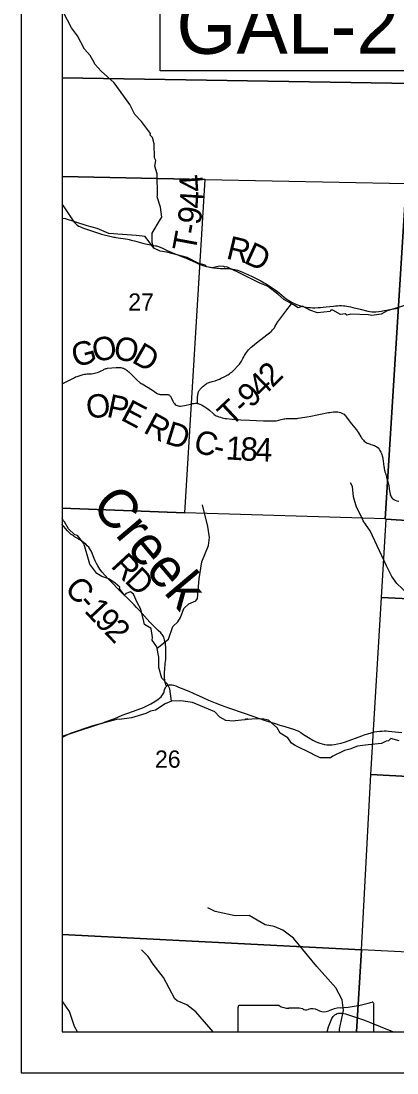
# Model space of a CAD drawing. Extents: x 0 to 34, y 0 to 22.
# Drawn here: x 2 to 2.913, y 14 to 16.555 of the extents above; entities that cross this region are included whole.
import ezdxf

# ---------------------------------------------------------------- set-up
doc = ezdxf.new("R2010")
doc.units = 0
for name, color, linetype in [('Default', 7, 'Continuous'), ('GM_X_County_Road', 7, 'Continuous'), ('GM_X_County_Road_Text', 7, 'Continuous'), ('GM_X_Minor_River', 7, 'Continuous'), ('GM_X_Minor_River_Text', 7, 'Continuous'), ('GM_X_Section', 7, 'Continuous'), ('GM_X_Section_Text', 7, 'Continuous'), ('GM_X_State_Route', 7, 'Continuous'), ('GM_X_State_Shield', 7, 'Continuous'), ('GM_X_Township_Road', 7, 'Continuous'), ('GM_X_Township_Road_Text', 7, 'Continuous'), ('SH_Cut_Line', 7, 'Continuous'), ('SH_Data', 7, 'Continuous'), ('TX_P_1', 7, 'Continuous')]:
    doc.layers.add(name, color=color, linetype=linetype)

msp = doc.modelspace()

# ---------------------------------------------------------------- linework, layer by layer
at = {"layer": 'Default'}
for points in [[(2.1, 19.5179), (2.1, 14.1), (5.687, 14.1), (5.785, 14.1504), (5.9145, 14.1963), (5.9273, 14.1959), (5.9341, 14.3014), (6.0001, 15.328), (6.0418, 15.9539), (6.0633, 16.2368), (6.0901, 16.6706), (6.1151, 17.0743), (6.1723, 18.0255), (6.1917, 18.3385), (6.2282, 18.9116), (6.2536, 19.3066), (5.4875, 19.3459), (4.7013, 19.3856), (4.4284, 19.3984), (3.7007, 19.4348)], [(2.1, 16.6219), (2.1, 16.4177), (2.9504, 16.4035), (2.9626, 16.5982)], [(2.1, 16.4177), (2.1, 16.178), (2.4468, 16.1708), (2.9352, 16.1608), (2.9504, 16.4035)], [(2.1, 16.178), (2.1, 15.3718), (2.3978, 15.3611), (2.4468, 16.1708)], [(2.1, 15.3718), (2.1, 14.3367), (2.8265, 14.2988), (2.8494, 14.7254), (2.8751, 15.155), (2.8868, 15.3457), (2.8841, 15.3459), (2.3978, 15.3611)], [(2.1, 14.3367), (2.1, 14.1), (2.815, 14.1), (2.8265, 14.2988)], [(2.815, 14.1), (3.8426, 14.1), (3.8519, 14.2476), (2.8265, 14.2988)]]:
    msp.add_lwpolyline(points, close=True, dxfattribs=at)
at = {"layer": 'GM_X_County_Road'}
for points in [[(2.1, 16.1097), (2.1071, 16.0992), (2.1231, 16.0749), (2.125, 16.0722), (2.1271, 16.0696), (2.129, 16.0672), (2.1314, 16.0643), (2.1339, 16.0619), (2.1367, 16.0596), (2.1402, 16.0573), (2.1442, 16.0552), (2.1477, 16.0536), (2.1519, 16.052), (2.1854, 16.041), (2.1903, 16.0395), (2.1954, 16.0381), (2.2187, 16.032), (2.222, 16.0313), (2.2252, 16.0307), (2.2279, 16.0301), (2.2306, 16.0297), (2.2594, 16.0253), (2.2624, 16.0247), (2.2652, 16.0241), (2.2676, 16.0235), (2.2705, 16.0227), (2.2752, 16.0214)], [(2.2752, 16.0214), (2.2923, 16.0165), (2.2955, 16.0157), (2.2982, 16.0151), (2.3263, 16.0097), (2.3288, 16.0091), (2.3312, 16.0084), (2.3336, 16.0076), (2.3357, 16.0069), (2.3379, 16.0061), (2.3399, 16.0053), (2.3423, 16.0043), (2.3548, 15.9983), (2.3666, 15.9928), (2.3964, 15.9813), (2.3993, 15.9801), (2.4027, 15.9787), (2.4061, 15.9773), (2.4098, 15.9757), (2.4247, 15.9688), (2.4312, 15.9659), (2.4371, 15.9636), (2.4418, 15.9618), (2.4468, 15.9602), (2.4509, 15.9591), (2.455, 15.9581), (2.4589, 15.9574), (2.4629, 15.9567), (2.4672, 15.9561), (2.4712, 15.9556), (2.4753, 15.9551), (2.4793, 15.9548), (2.4842, 15.9545), (2.5062, 15.9539), (2.509, 15.9537), (2.5114, 15.9534), (2.5138, 15.953), (2.5192, 15.9519), (2.5254, 15.9502), (2.5319, 15.948), (2.5381, 15.9455), (2.5452, 15.9424), (2.5521, 15.9392), (2.5594, 15.9356), (2.5822, 15.9243), (2.5866, 15.922), (2.5907, 15.9198), (2.5951, 15.9173), (2.5989, 15.915), (2.6029, 15.9123), (2.6078, 15.9091), (2.6147, 15.9044), (2.6225, 15.8985), (2.6276, 15.8942), (2.6332, 15.8896), (2.6393, 15.8844), (2.6402, 15.8837)], [(2.6402, 15.8837), (2.6429, 15.8817), (2.6458, 15.8796), (2.6483, 15.8779), (2.6502, 15.8767), (2.6588, 15.8719), (2.6693, 15.8669), (2.6741, 15.8649), (2.6785, 15.8633), (2.6835, 15.8619), (2.688, 15.8608), (2.6926, 15.86), (2.6975, 15.8595), (2.7033, 15.8593), (2.7082, 15.8591), (2.7133, 15.8591), (2.7219, 15.8594), (2.7272, 15.8597), (2.7336, 15.8602), (2.7409, 15.8609), (2.759, 15.8631), (2.764, 15.8636), (2.7689, 15.864), (2.7736, 15.8641), (2.7779, 15.8641), (2.783, 15.8638), (2.7872, 15.8634), (2.7913, 15.8628), (2.7955, 15.862), (2.8005, 15.8609), (2.8061, 15.8596), (2.824, 15.8551), (2.842, 15.8507), (2.8472, 15.8497), (2.8519, 15.8491), (2.8568, 15.8488), (2.8614, 15.8489), (2.8688, 15.8496), (2.8746, 15.8505), (2.896, 15.8544), (2.9157, 15.8581)], [(2.1, 15.6739), (2.1164, 15.6821), (2.1275, 15.6882), (2.1299, 15.6895), (2.1325, 15.6908), (2.1361, 15.6923), (2.1412, 15.6939), (2.1507, 15.6967), (2.154, 15.6974), (2.1574, 15.6979), (2.1609, 15.6981), (2.1641, 15.6983), (2.1676, 15.6984), (2.1715, 15.6987), (2.1751, 15.6991), (2.1786, 15.6997), (2.182, 15.7006), (2.186, 15.7017), (2.1894, 15.703), (2.1931, 15.7047), (2.2, 15.7084), (2.202, 15.7094), (2.204, 15.7102), (2.2061, 15.711), (2.208, 15.7115), (2.21, 15.7118), (2.231, 15.7137), (2.2335, 15.7139), (2.2358, 15.714), (2.2382, 15.714), (2.2405, 15.7138), (2.2427, 15.7136), (2.245, 15.7131), (2.2471, 15.7125), (2.2489, 15.7118), (2.2511, 15.7107), (2.2533, 15.7094), (2.2554, 15.7081), (2.2576, 15.7064), (2.2597, 15.7048), (2.262, 15.7029), (2.2644, 15.7007), (2.2669, 15.6982), (2.2821, 15.6828), (2.2895, 15.6767), (2.2914, 15.6753), (2.2939, 15.6738), (2.319, 15.6584), (2.3284, 15.6522), (2.3305, 15.651), (2.3325, 15.6501), (2.3344, 15.6494), (2.336, 15.6489), (2.3376, 15.6486), (2.3386, 15.6484), (2.3395, 15.6484), (2.3455, 15.6484), (2.3515, 15.6485), (2.3535, 15.6485), (2.3552, 15.6484), (2.3568, 15.6482), (2.3584, 15.6477), (2.3596, 15.647), (2.3607, 15.6462), (2.3617, 15.6453), (2.3627, 15.644), (2.3636, 15.6425), (2.3646, 15.6406), (2.3689, 15.6316), (2.3706, 15.6288), (2.3723, 15.6264), (2.3744, 15.6242), (2.3769, 15.6224), (2.3791, 15.6213), (2.3814, 15.6206), (2.3845, 15.6201), (2.3876, 15.62), (2.3919, 15.6203), (2.3967, 15.6211), (2.4123, 15.6249), (2.4167, 15.626), (2.4208, 15.6267), (2.4236, 15.6269), (2.4259, 15.627), (2.4283, 15.6267), (2.43, 15.6263), (2.4316, 15.6258), (2.4343, 15.6247), (2.4381, 15.6229), (2.4421, 15.6208), (2.4466, 15.6181), (2.451, 15.6151), (2.4541, 15.6126), (2.4575, 15.6098), (2.4669, 15.6017), (2.4688, 15.6), (2.4712, 15.5983), (2.4742, 15.5966), (2.4773, 15.5953), (2.4807, 15.5941), (2.4844, 15.5929), (2.4886, 15.5917), (2.492, 15.5909), (2.4956, 15.5903), (2.4992, 15.5898), (2.5129, 15.5883), (2.5229, 15.5874), (2.5276, 15.5871), (2.5335, 15.5868), (2.5547, 15.5862), (2.589, 15.5841), (2.6018, 15.5839), (2.6138, 15.5841), (2.6169, 15.5842), (2.6196, 15.5844), (2.6226, 15.5848), (2.6257, 15.5855), (2.6318, 15.5873), (2.6351, 15.5883), (2.6379, 15.589), (2.6406, 15.5894), (2.644, 15.5897), (2.668, 15.5899), (2.6704, 15.5901), (2.6728, 15.5904), (2.6998, 15.5947), (2.7468, 15.6041), (2.7503, 15.6047), (2.7543, 15.6053), (2.7586, 15.6058), (2.7622, 15.606), (2.7657, 15.6061), (2.7691, 15.6059), (2.7725, 15.6053), (2.776, 15.6042), (2.7795, 15.6029), (2.7823, 15.6015), (2.7845, 15.6002), (2.7867, 15.5983), (2.7883, 15.5965), (2.79, 15.5943), (2.8029, 15.5773), (2.8144, 15.5623), (2.8161, 15.5602), (2.8175, 15.5583), (2.8194, 15.5554), (2.8251, 15.5456), (2.8266, 15.5435), (2.828, 15.5415), (2.8314, 15.5374), (2.8336, 15.5352), (2.836, 15.5332), (2.8381, 15.5317), (2.8408, 15.5302), (2.8435, 15.5291), (2.8463, 15.5281), (2.8498, 15.5271), (2.8526, 15.5263), (2.8555, 15.5253), (2.8584, 15.5243), (2.8612, 15.5229), (2.8643, 15.5209), (2.867, 15.5185), (2.8697, 15.5152), (2.8717, 15.5121), (2.874, 15.5078), (2.8752, 15.505), (2.8763, 15.5024), (2.8773, 15.4993), (2.8779, 15.4965), (2.8784, 15.4931), (2.8813, 15.4734), (2.8817, 15.4708), (2.8821, 15.4682), (2.8839, 15.4606), (2.8848, 15.4571), (2.8876, 15.4471), (2.8902, 15.4387), (2.8909, 15.4363), (2.8917, 15.4333), (2.8924, 15.43), (2.8929, 15.4265), (2.8947, 15.4137), (2.8953, 15.4098), (2.8961, 15.4068), (2.8968, 15.4043), (2.8978, 15.4018), (2.899, 15.3996), (2.9006, 15.3972), (2.9028, 15.395), (2.9054, 15.3931), (2.9089, 15.3916), (2.9127, 15.3902), (2.9172, 15.3888)], [(2.3531, 14.9394), (2.3517, 14.9441), (2.3503, 14.9487), (2.3496, 14.9516), (2.3491, 14.9547), (2.3486, 14.959), (2.3485, 14.9629), (2.3485, 14.9673), (2.3486, 14.9709), (2.3488, 14.9746), (2.3493, 14.9802), (2.3504, 14.9948), (2.3513, 15.0048), (2.3515, 15.0106), (2.3516, 15.0181), (2.3517, 15.0257), (2.3516, 15.0307), (2.3513, 15.0351), (2.351, 15.0395), (2.3505, 15.0439), (2.3496, 15.0481), (2.3485, 15.0522), (2.3475, 15.0556), (2.3466, 15.0583), (2.3457, 15.0606), (2.3444, 15.0629), (2.3429, 15.0651), (2.3414, 15.0671), (2.3395, 15.069), (2.3331, 15.0752), (2.3131, 15.0952), (2.2876, 15.1233), (2.2806, 15.1308), (2.2744, 15.1372), (2.2675, 15.1442), (2.2599, 15.1517), (2.2453, 15.1652), (2.2116, 15.2005), (2.2033, 15.2096), (2.1971, 15.2169), (2.1916, 15.2241), (2.1867, 15.2317), (2.1832, 15.2377), (2.18, 15.244), (2.1777, 15.2496), (2.1735, 15.2606), (2.1716, 15.2652), (2.1696, 15.2695), (2.1673, 15.2734), (2.1644, 15.2771), (2.1609, 15.2807), (2.157, 15.2845), (2.1541, 15.287), (2.1515, 15.289), (2.148, 15.2916), (2.144, 15.2941), (2.1407, 15.2962), (2.1377, 15.298), (2.1302, 15.3025), (2.1271, 15.3045), (2.1246, 15.3062), (2.1218, 15.3084), (2.118, 15.3119), (2.113, 15.3169), (2.1081, 15.3224), (2.1041, 15.3272), (2.1002, 15.3319), (2.1, 15.3322)], [(2.1, 14.818), (2.1248, 14.8265), (2.1914, 14.8479), (2.1977, 14.85), (2.2045, 14.8526), (2.2277, 14.8615), (2.2458, 14.8689), (2.271, 14.8779), (2.2909, 14.8852), (2.2977, 14.8882), (2.3056, 14.892), (2.3149, 14.8967), (2.325, 14.9024), (2.3284, 14.9045), (2.3319, 14.9069), (2.3362, 14.9103), (2.3401, 14.9141), (2.3437, 14.9185), (2.3455, 14.9214), (2.3466, 14.9235), (2.3472, 14.9255), (2.348, 14.928), (2.3488, 14.9306), (2.3496, 14.9331), (2.3505, 14.9353), (2.3517, 14.9375), (2.3523, 14.9385), (2.3531, 14.9394), (2.354, 14.94), (2.355, 14.9409), (2.3573, 14.9421), (2.36, 14.9428), (2.3623, 14.9432), (2.3646, 14.9432), (2.3671, 14.9428), (2.3704, 14.9421), (2.3757, 14.9403), (2.3826, 14.9376), (2.3889, 14.935), (2.4073, 14.9275), (2.4181, 14.9229), (2.4416, 14.912), (2.4553, 14.9057), (2.4717, 14.8988), (2.4862, 14.8932), (2.5037, 14.8867), (2.5419, 14.8737), (2.5926, 14.8566), (2.6168, 14.8487), (2.6286, 14.8449), (2.6405, 14.8415), (2.654, 14.8376), (2.6616, 14.835), (2.6684, 14.8324), (2.674, 14.83), (2.6792, 14.8272), (2.6838, 14.8241), (2.6902, 14.8201), (2.698, 14.8151), (2.7087, 14.8084), (2.7153, 14.8049), (2.7205, 14.8026), (2.7259, 14.8008), (2.7313, 14.7993), (2.7367, 14.7981), (2.7426, 14.7973), (2.7485, 14.797), (2.7547, 14.7972), (2.7612, 14.7978), (2.7684, 14.7993), (2.7774, 14.8015), (2.7877, 14.8044), (2.8273, 14.8189), (2.8354, 14.8219), (2.8424, 14.8242), (2.8501, 14.8265), (2.8574, 14.8284), (2.8642, 14.8295), (2.8711, 14.8303), (2.8765, 14.8307), (2.8823, 14.8309), (2.8869, 14.8309), (2.8921, 14.8306), (2.9002, 14.8299), (2.925, 14.827)]]:
    msp.add_lwpolyline(points, dxfattribs=at)
at = {"layer": 'GM_X_Minor_River'}
for points in [[(2.3146, 16.2822), (2.2923, 16.3118), (2.2764, 16.3281), (2.2646, 16.3524), (2.2283, 16.4021), (2.2253, 16.4059), (2.1943, 16.4339), (2.1799, 16.4495), (2.1742, 16.4601), (2.1678, 16.4719), (2.1538, 16.4874), (2.1371, 16.5193), (2.1227, 16.5387), (2.1023, 16.5778), (2.1, 16.5796)], [(2.9346, 15.8653), (2.8896, 15.8511), (2.8745, 15.8435), (2.8518, 15.8404), (2.8435, 15.8419), (2.8011, 15.8433), (2.7913, 15.841), (2.7875, 15.844), (2.7758, 15.8428), (2.7569, 15.8534), (2.752, 15.8527), (2.7505, 15.85), (2.7202, 15.8465), (2.7013, 15.8533), (2.6832, 15.8624), (2.673, 15.8589), (2.662, 15.8657), (2.6382, 15.879), (2.6234, 15.8919), (2.5985, 15.9112), (2.5799, 15.9184), (2.541, 15.9377), (2.4998, 15.9581), (2.4948, 15.9577), (2.4922, 15.9592), (2.4816, 15.9603), (2.4638, 15.9557), (2.4514, 15.958), (2.4468, 15.9625), (2.4298, 15.967), (2.4033, 15.981), (2.3538, 15.9942), (2.3379, 15.9961), (2.3224, 16.0033), (2.3183, 16.0177), (2.3182, 16.0401), (2.339, 16.0744), (2.342, 16.0786), (2.3386, 16.1029), (2.3306, 16.1287), (2.3318, 16.1314), (2.331, 16.1842), (2.3253, 16.2032), (2.3271, 16.2169), (2.3245, 16.2229), (2.3233, 16.2568), (2.3195, 16.2723), (2.3135, 16.2784), (2.3146, 16.2822)], [(2.3224, 16.0033), (2.3016, 16.0321), (2.2793, 16.0347), (2.2131, 16.0395), (2.1852, 16.0512), (2.1602, 16.0576), (2.1058, 16.0754), (2.1, 16.0753)], [(3.1037, 14.8257), (3.0772, 14.885), (3.0702, 14.9175), (3.0642, 14.9431), (3.0482, 14.9873), (3.0249, 15.029), (2.9823, 15.0843), (2.9647, 15.113), (2.9527, 15.1422), (2.9405, 15.1631), (2.9129, 15.189), (2.9002, 15.2061), (2.8874, 15.2323), (2.848, 15.3171), (2.831, 15.3412), (2.8274, 15.3493), (2.815, 15.3744), (2.8078, 15.3997), (2.8048, 15.4248), (2.8005, 15.4333)], [(2.3308, 15.0319), (2.358, 15.0541), (2.3687, 15.0842), (2.3808, 15.0956), (2.3875, 15.1067), (2.395, 15.1285), (2.4074, 15.1399), (2.4247, 15.1473), (2.4282, 15.1529), (2.4327, 15.2006), (2.4389, 15.2414), (2.4552, 15.2811), (2.4577, 15.3008), (2.4536, 15.3275), (2.4408, 15.3803)], [(2.3654, 14.9035), (2.3612, 14.9328), (2.3559, 14.9442), (2.3423, 14.9594), (2.3343, 14.9848), (2.3347, 15.0103), (2.3297, 15.035), (2.3188, 15.0517), (2.3195, 15.0581), (2.3161, 15.0794), (2.2998, 15.0896), (2.2979, 15.0964), (2.2907, 15.1265), (2.2824, 15.1428), (2.2729, 15.1633), (2.2661, 15.169), (2.2548, 15.1644), (2.2533, 15.1625), (2.2514, 15.1606), (2.2389, 15.1773), (2.24, 15.1799), (2.2283, 15.1902), (2.2132, 15.2004), (2.1961, 15.2057), (2.1837, 15.2136), (2.167, 15.236), (2.1609, 15.2584), (2.1522, 15.2865), (2.1375, 15.3055), (2.131, 15.3074), (2.1155, 15.3218), (2.1053, 15.3392), (2.1034, 15.3415), (2.1, 15.3472)], [(2.4829, 14.8643), (2.4709, 14.8776), (2.4459, 14.8882), (2.4168, 14.8999), (2.3881, 14.9044), (2.3654, 14.9035), (2.3503, 14.8967), (2.3269, 14.8814), (2.3148, 14.8791), (2.3034, 14.873), (2.2679, 14.8627), (2.2388, 14.8584), (2.235, 14.8595), (2.1742, 14.8431), (2.1194, 14.8243), (2.1, 14.8153)], [(2.9185, 14.8072), (2.8981, 14.8129), (2.8928, 14.8072), (2.8868, 14.8064), (2.8751, 14.8006), (2.8429, 14.7975), (2.8168, 14.794), (2.7987, 14.7868), (2.7859, 14.7837), (2.7575, 14.7692), (2.7518, 14.7658), (2.7265, 14.7653), (2.708, 14.7748), (2.7053, 14.7763), (2.6656, 14.7959), (2.6566, 14.8013), (2.6479, 14.8138), (2.6297, 14.8251), (2.6221, 14.8388), (2.6013, 14.857), (2.5858, 14.8604), (2.5605, 14.8595), (2.5518, 14.8588), (2.5495, 14.861), (2.5473, 14.858), (2.545, 14.8603), (2.5439, 14.858), (2.52, 14.8556), (2.517, 14.8549), (2.4974, 14.8564), (2.4827, 14.8644)], [(2.7734, 14.1), (2.7736, 14.106), (2.7829, 14.1516), (2.7796, 14.1779), (2.7642, 14.2065), (2.7185, 14.2585), (2.662, 14.3271), (2.6361, 14.3469), (2.6149, 14.3556), (2.5931, 14.3601), (2.5541, 14.3822), (2.52, 14.3817), (2.4716, 14.392), (2.4533, 14.401)], [(2.4663, 14.1), (2.4244, 14.1481), (2.403, 14.1659), (2.3795, 14.175), (2.3736, 14.1797), (2.3461, 14.2319), (2.3206, 14.2642), (2.3087, 14.2832), (2.2925, 14.2992)], [(2.137, 14.1), (2.1301, 14.1126), (2.1173, 14.1494), (2.1, 14.1751)]]:
    msp.add_lwpolyline(points, dxfattribs=at)
at = {"layer": 'GM_X_Section'}
for points in [[(2.9352, 16.1608), (2.8841, 15.3459), (2.3978, 15.3611), (2.4468, 16.1708)], [(3.0046, 16.1593), (2.9664, 15.604), (2.9483, 15.3412), (2.8868, 15.3457), (2.8841, 15.3459), (2.9352, 16.1608)], [(2.9483, 15.3412), (3.9173, 15.2973), (3.9051, 15.1052), (2.8751, 15.155), (2.8868, 15.3457)], [(2.8751, 15.155), (3.9051, 15.1052), (3.8776, 14.6701), (2.8494, 14.7254)], [(3.8776, 14.6701), (3.8519, 14.2476), (2.8265, 14.2988), (2.8494, 14.7254)]]:
    msp.add_lwpolyline(points, close=True, dxfattribs=at)
at = {"layer": 'GM_X_State_Route'}
msp.add_lwpolyline([(2.7434, 14.1), (2.7469, 14.112), (2.7482, 14.1161), (2.7496, 14.1202), (2.7513, 14.1245), (2.753, 14.1283), (2.7549, 14.132), (2.7568, 14.135), (2.7583, 14.1372), (2.7603, 14.1393), (2.7625, 14.1413), (2.7651, 14.143), (2.7679, 14.1444), (2.771, 14.1452), (2.7743, 14.1454), (2.7776, 14.1453), (2.7806, 14.1449), (2.7838, 14.1443), (2.7879, 14.1433), (2.8028, 14.1388), (2.8315, 14.1292), (2.8386, 14.1266), (2.8464, 14.1236), (2.898, 14.102), (2.9025, 14.1005), (2.9043, 14.1)], dxfattribs=at)
at = {"layer": 'GM_X_State_Shield'}
msp.add_line((2.6267, 14.1635), (2.5301, 14.1635), dxfattribs=at)
msp.add_lwpolyline([(2.5269, 14.16), (2.5269, 14.1), (2.8565, 14.1), (2.8565, 14.1687)], dxfattribs=at)
for centre, major_axis, start_param, end_param in [((2.5307, 14.1605), (0.00382, 0), 1.727492, 3.291633), ((2.6497, 14.1867), (0.037, 0), 4.042888, 4.731792), ((2.662, 14.0512), (0.133, 0), 1.404758, 1.657859), ((2.7078, 14.1384), (0.0222, 0), 0.950623, 2.079405), ((2.7837, 14.1024), (0.0703, 0), 1.699012, 2.107814), ((2.7391, 14.4363), (0.3495, 0), 4.814394, 5.042369), ((2.8529, 14.1689), (0.00367, 0), 6.197627, 7.989034), ((2.6922, 14.1615), (0.0107, 0), 3.836095, 5.185415), ((2.7365, 14.1701), (0.0267, 0), 4.08156, 5.145723)]:
    msp.add_ellipse(centre, major_axis=major_axis, ratio=0.8, start_param=start_param, end_param=end_param, dxfattribs=at)
at = {"layer": 'GM_X_Township_Road'}
msp.add_lwpolyline([(2.4283, 15.6267), (2.4285, 15.6318), (2.4288, 15.6406), (2.4289, 15.6435), (2.4291, 15.646), (2.4295, 15.6485), (2.4299, 15.6506), (2.4304, 15.6526), (2.4311, 15.6545), (2.4319, 15.6562), (2.433, 15.6581), (2.4341, 15.6599), (2.4352, 15.6613), (2.4364, 15.6628), (2.4382, 15.6646), (2.4403, 15.6667), (2.4423, 15.6685), (2.4444, 15.6704), (2.4464, 15.6719), (2.4486, 15.6734), (2.4504, 15.6744), (2.4523, 15.6754), (2.4545, 15.6764), (2.4568, 15.6773), (2.4589, 15.678), (2.4614, 15.6788), (2.4641, 15.6796), (2.4712, 15.6818), (2.477, 15.6837), (2.4816, 15.6855), (2.4862, 15.6878), (2.4947, 15.6923), (2.5023, 15.6963), (2.5061, 15.6986), (2.5091, 15.7005), (2.5117, 15.7027), (2.5151, 15.7057), (2.5288, 15.72), (2.5306, 15.7221), (2.5325, 15.7245), (2.5339, 15.7266), (2.5353, 15.729), (2.5387, 15.7355), (2.5409, 15.7396), (2.543, 15.7433), (2.545, 15.7466), (2.5472, 15.7501), (2.5497, 15.7534), (2.5526, 15.7569), (2.5557, 15.7602), (2.5591, 15.7632), (2.5623, 15.7658), (2.572, 15.7734), (2.6074, 15.8016), (2.6093, 15.8032), (2.611, 15.8049), (2.6125, 15.8067), (2.6138, 15.8083), (2.6153, 15.8104), (2.6166, 15.8124), (2.622, 15.8222), (2.6232, 15.8241), (2.6243, 15.826), (2.6259, 15.8282), (2.6459, 15.8536), (2.6544, 15.8653), (2.6588, 15.8719)], dxfattribs=at)
at = {"layer": 'SH_Cut_Line'}
msp.add_lwpolyline([(2.1, 20.9), (2.1, 14.1), (5.687, 14.1)], dxfattribs=at)
at = {"layer": 'SH_Data'}
for p, q in [((2, 21), (2, 14)), ((2.1, 20.9), (2.1, 14.1)), ((2.1, 14.1), (8.9, 14.1)), ((2.1, 14.1), (2.1, 14.1)), ((2, 14), (9, 14))]:
    msp.add_line(p, q, dxfattribs=at)
at = {"layer": 'TX_P_1'}
msp.add_lwpolyline([(2.3381, 16.6555), (3.6423, 16.6555), (3.6423, 16.4348), (2.3381, 16.4348)], close=True, dxfattribs=at)

# ---------------------------------------------------------------- texts
at = {"layer": 'GM_X_County_Road_Text'}
for s, rotation, p in [('R', 346.3358, (2.496, 15.979)), ('D', 335.3756, (2.5386, 15.9689)), ('G', 14.9251, (2.1311, 15.714)), ('O', 10.6302, (2.1783, 15.7266)), ('O', 348.754, (2.2217, 15.7358)), ('D', 330.2452, (2.2663, 15.7278)), ('O', 5.0846, (2.1604, 15.5897)), ('P', 347.959, (2.2058, 15.5944)), ('E', 332.2063, (2.2394, 15.5878)), ('R', 331.6612, (2.2946, 15.557)), ('D', 342.9484, (2.3469, 15.5301)), ('C', 344.7009, (2.4157, 15.51)), ('1', 356.5063, (2.4961, 15.4907)), ('8', 356.9001, (2.5315, 15.4885)), ('4', 357.717, (2.5673, 15.4866)), ('-', 347.826, (2.464, 15.4969)), ('R', 312.6728, (2.216, 15.2302)), ('D', 315.1012, (2.2494, 15.194)), ('C', 311.4154, (2.1035, 15.1752)), ('-', 312.6481, (2.1353, 15.1392)), ('1', 313.1524, (2.1515, 15.1216)), ('9', 313.6665, (2.1758, 15.0957)), ('2', 313.7988, (2.2001, 15.0703))]:
    msp.add_text(s, height=0.0568, rotation=rotation, dxfattribs=at).set_placement(p)
at = {"layer": 'GM_X_Minor_River_Text'}
msp.add_text('Creek', height=0.09469, rotation=310.1368, dxfattribs=at).set_placement((2.168, 15.3769))
at = {"layer": 'GM_X_Section_Text'}
for s, p in [('27', (2.2603, 15.8519)), ('26', (2.3253, 14.7415))]:
    msp.add_text(s, height=0.04186, rotation=0, dxfattribs=at).set_placement(p)
at = {"layer": 'GM_X_Township_Road_Text'}
for s, rotation, p in [('4', 94.394, (2.4435, 16.1424)), ('4', 86.3482, (2.4413, 16.0988)), ('9', 81.0918, (2.4353, 16.0586)), ('-', 79.8371, (2.4309, 16.0343)), ('T', 79.5276, (2.4231, 15.9922)), ('2', 45.3268, (2.6106, 15.6631)), ('4', 43.961, (2.5844, 15.6378)), ('9', 43.407, (2.5585, 15.6133)), ('T', 43.0875, (2.5102, 15.5681)), ('-', 43.1508, (2.5413, 15.5972))]:
    msp.add_text(s, height=0.0568, rotation=rotation, dxfattribs=at).set_placement(p)
at = {"layer": 'TX_P_1'}
msp.add_text('GAL-218-4.81', height=0.14, dxfattribs=at).set_placement((2.3774, 16.4758))

doc.saveas('drawing.dxf')
